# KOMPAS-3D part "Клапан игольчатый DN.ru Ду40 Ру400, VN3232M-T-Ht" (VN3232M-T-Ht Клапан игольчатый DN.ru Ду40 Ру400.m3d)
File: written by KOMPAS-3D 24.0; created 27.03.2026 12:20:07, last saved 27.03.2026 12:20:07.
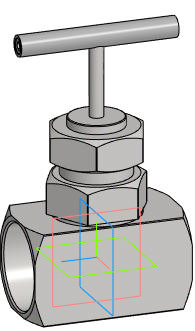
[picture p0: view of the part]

Document properties: Автор: Илья; Полное имя файла: D:\Обмен\Заказы с фриланса\DN.ru\VNxxM-T-Ht Клапан игольчатый DN.ru Ду8-50 Ру400\VN3232M-T-Ht Клапан игольчатый DN.ru Ду8-50 Ру400\DN40\VN3232M-T-Ht Клапан игольчатый DN.ru Ду40 Ру400.m3d

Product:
- Body: Body4  | qty 1
    Масса: 2.135076
- Part/product: Клапан игольчатый DN.ru Ду40 Ру400  | designation VN3232M-T-Ht
    Масса: 2
    Раздел спецификации: Прочие изделия
    Примечание: D090-02135

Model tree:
1. Body4  (labels: Body4)

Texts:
  VN3232M-T-Ht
